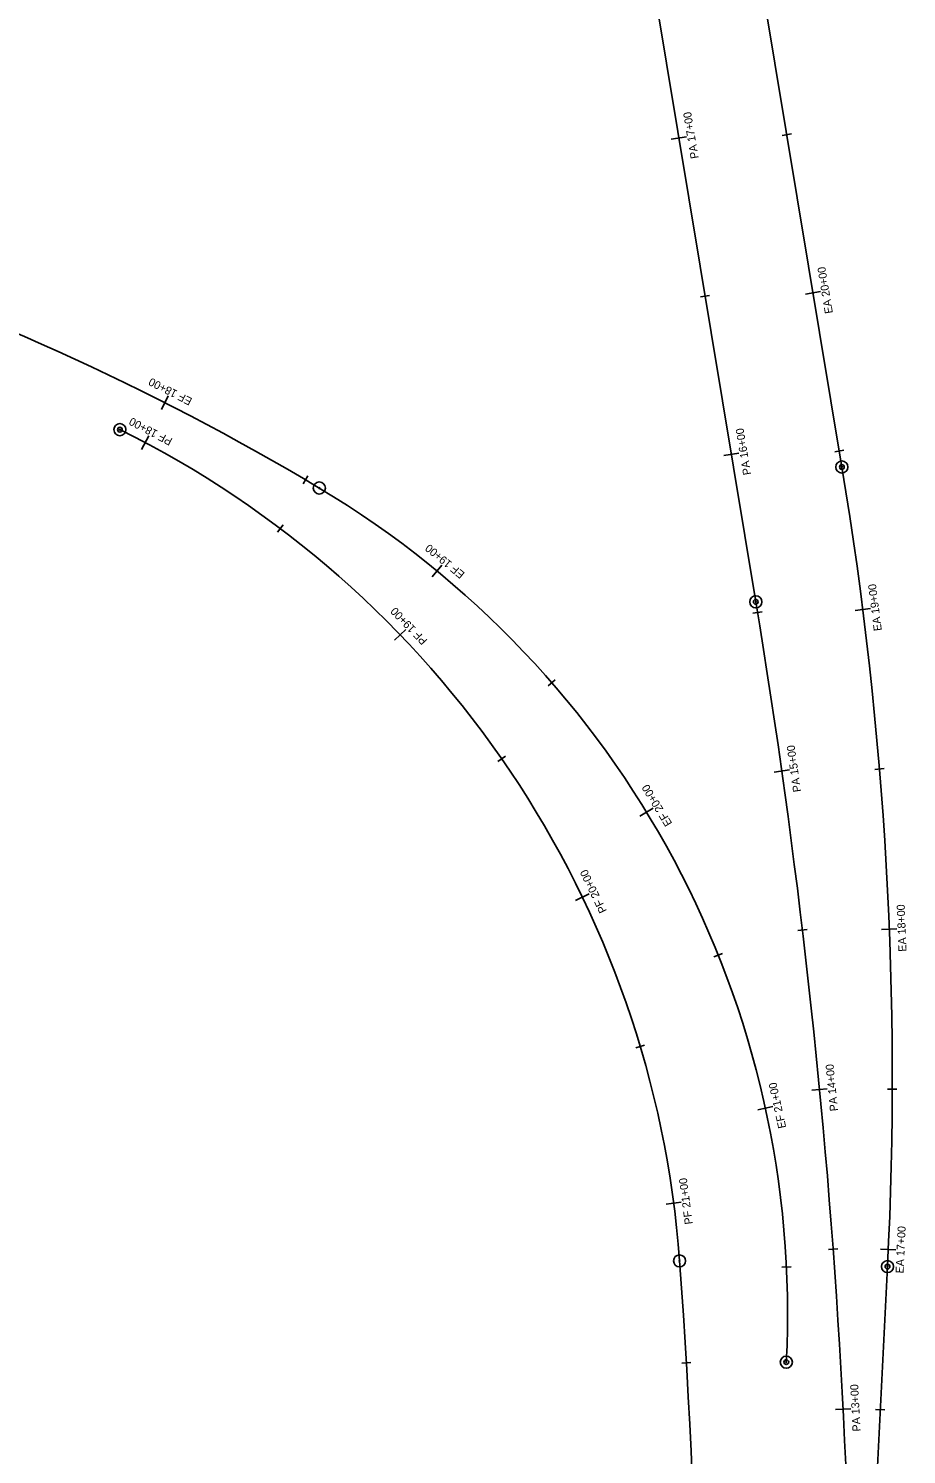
# Model space of a CAD drawing. Extents: x 950864 to 953360, y 1126381 to 1128045.
# Drawn here: x 951848.2 to 952121.9, y 1126674.4 to 1127119 of the extents above; entities that cross this region are included whole.
import ezdxf

# ---------------------------------------------------------------- set-up
doc = ezdxf.new("R2010")
doc.units = 0
doc.layers.add('Existing', color=7, linetype='Continuous')
doc.layers.add('Proposed', color=7, linetype='Continuous')

msp = doc.modelspace()

# ---------------------------------------------------------------- linework, layer by layer
at = {"layer": 'Existing'}
for p, q in [((952101.78, 1126982.28), (951986.82, 1127675.69)), ((952098.59, 1126388.66), (952115.99, 1126732.93))]:
    msp.add_line(p, q, dxfattribs=at)
for points in [[(952083.17, 1127085.71), (952086.02, 1127086.18)], [(952090.41, 1127036.23), (952095.14, 1127037.01)], [(951891.79, 1127004.48), (951889.62, 1127000.2)], [(952099.53, 1126987.06), (952102.37, 1126987.53)], [(951935.27, 1126979.54), (951933.8, 1126977.06)], [(951977.1, 1126951.7), (951974.05, 1126947.99)], [(952105.89, 1126937.53), (952110.65, 1126938.14)], [(952012.43, 1126915.93), (952010.26, 1126914.05)], [(952112.04, 1126887.99), (952114.91, 1126888.23)], [(952042.89, 1126875.94), (952038.79, 1126873.43)], [(952114.15, 1126838.11), (952118.94, 1126838.3)], [(952064.57, 1126830.58), (952061.9, 1126829.51)], [(952116.03, 1126788.23), (952118.91, 1126788.22)], [(952080.26, 1126782.82), (952075.57, 1126781.8)], [(952113.85, 1126738.35), (952118.64, 1126738.13)], [(952085.91, 1126732.87), (952083.04, 1126732.73)], [(952112.29, 1126688.38), (952115.17, 1126688.23)]]:
    msp.add_lwpolyline(points, dxfattribs=at)
for centre, radius in [((952101.78, 1126982.28), 1.89), ((952101.78, 1126982.28), 0.744), ((952101.78, 1126982.28), 0.154), ((951938.87, 1126975.73), 1.89), ((951938.87, 1126975.73), 0.154), ((952115.99, 1126732.93), 1.88), ((952115.99, 1126732.93), 0.747), ((952115.99, 1126732.93), 0.156), ((952084.44, 1126703.15), 1.89), ((952084.44, 1126703.15), 0.744), ((952084.44, 1126703.15), 0.154)]:
    msp.add_circle(centre, radius, dxfattribs=at)
for centre, radius, start, end in [((951528.09, 1126289.24), 800, 59.10473, 85.39079), ((950952.47, 1126791.73), 1165, 357.10692, 9.4135), ((951784.83, 1126718.3), 300, 357.1069, 59.1047)]:
    msp.add_arc(centre, radius, start, end, dxfattribs=at)
at = {"layer": 'Proposed'}
msp.add_line((952074.92, 1126940.23), (951969.89, 1127573.74), dxfattribs=at)
for points in [[(952048.57, 1127084.5), (952053.31, 1127085.28)], [(952057.7, 1127035.33), (952060.54, 1127035.8)], [(951885.68, 1126992.03), (951883.43, 1126987.79)], [(952064.93, 1126985.84), (952069.66, 1126986.63)], [(951927.56, 1126964.25), (951925.82, 1126961.95)], [(952074.05, 1126936.67), (952076.89, 1126937.14)], [(951965.79, 1126931.62), (951962.33, 1126928.29)], [(951996.9, 1126892.15), (951994.54, 1126890.5)], [(952080.65, 1126887.15), (952085.4, 1126887.82)], [(952023.04, 1126849.22), (952018.71, 1126847.13)], [(952088.04, 1126837.73), (952090.9, 1126838.07)], [(952040.28, 1126802), (952037.52, 1126801.18)], [(952092.42, 1126787.96), (952097.2, 1126788.42)], [(952051.71, 1126753.06), (952046.95, 1126752.43)], [(952097.6, 1126738.26), (952100.48, 1126738.47)], [(952054.72, 1126703), (952051.85, 1126702.83)], [(952099.76, 1126688.34), (952104.55, 1126688.59)]]:
    msp.add_lwpolyline(points, dxfattribs=at)
for centre, radius in [((951876.7, 1126993.93), 1.88), ((951876.7, 1126993.93), 0.747), ((951876.7, 1126993.93), 0.156), ((952074.92, 1126940.23), 1.89), ((952074.92, 1126940.23), 0.744), ((952074.92, 1126940.23), 0.154), ((952051.18, 1126734.71), 1.89), ((952051.18, 1126734.71), 0.154)]:
    msp.add_circle(centre, radius, dxfattribs=at)
for centre, radius, start, end in [((951737.03, 1126711.59), 315, 4.2083, 63.6784), ((949865.09, 1126573.85), 2240, 357.10692, 9.4135), ((949865.09, 1126573.85), 2192, 357.10692, 4.20829)]:
    msp.add_arc(centre, radius, start, end, dxfattribs=at)

# ---------------------------------------------------------------- texts
at = {"layer": 'Existing'}
for s, rotation, p in [('EA 20+00', 99.4135, (952098.98, 1127030.32)), ('EF 18+00', 153.0466, (951899.46, 1127003.6)), ('EF 19+00', 140.5178, (951984.4, 1126949.17)), ('EA 19+00', 97.2046, (952114.23, 1126931.3)), ('EF 20+00', 121.4193, (952048.95, 1126871.16)), ('EA 18+00', 92.2865, (952121.92, 1126831.19)), ('EF 21+00', 102.3207, (952084.43, 1126776.32)), ('EA 17+00', 87.3684, (952120.99, 1126730.78))]:
    msp.add_text(s, height=2.496, rotation=rotation, dxfattribs=at).set_placement(p)
at = {"layer": 'Proposed'}
for s, rotation, p in [('PA 17+00', 99.4135, (952057.14, 1127078.62)), ('PF 18+00', 152.0741, (951893.3, 1126991.04)), ('PA 16+00', 99.4135, (952073.49, 1126979.99)), ('PF 19+00', 133.8849, (951972.72, 1126928.29)), ('PA 15+00', 98.0486, (952089.07, 1126881.08)), ('PF 20+00', 115.6958, (952028.58, 1126843.89)), ('PA 14+00', 95.4907, (952100.56, 1126781.51)), ('PF 21+00', 97.5067, (952055.31, 1126746.27)), ('PA 13+00', 92.9329, (952107.6, 1126681.58))]:
    msp.add_text(s, height=2.496, rotation=rotation, dxfattribs=at).set_placement(p)

doc.saveas('drawing.dxf')
